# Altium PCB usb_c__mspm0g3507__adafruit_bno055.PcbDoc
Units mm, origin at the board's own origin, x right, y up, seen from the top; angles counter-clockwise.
Board outline 92 x 60 mm, 2 copper layers (Top, Bottom), stack 0 mm thick; 44 components, 36 nets, 224 pads, 74 vias.
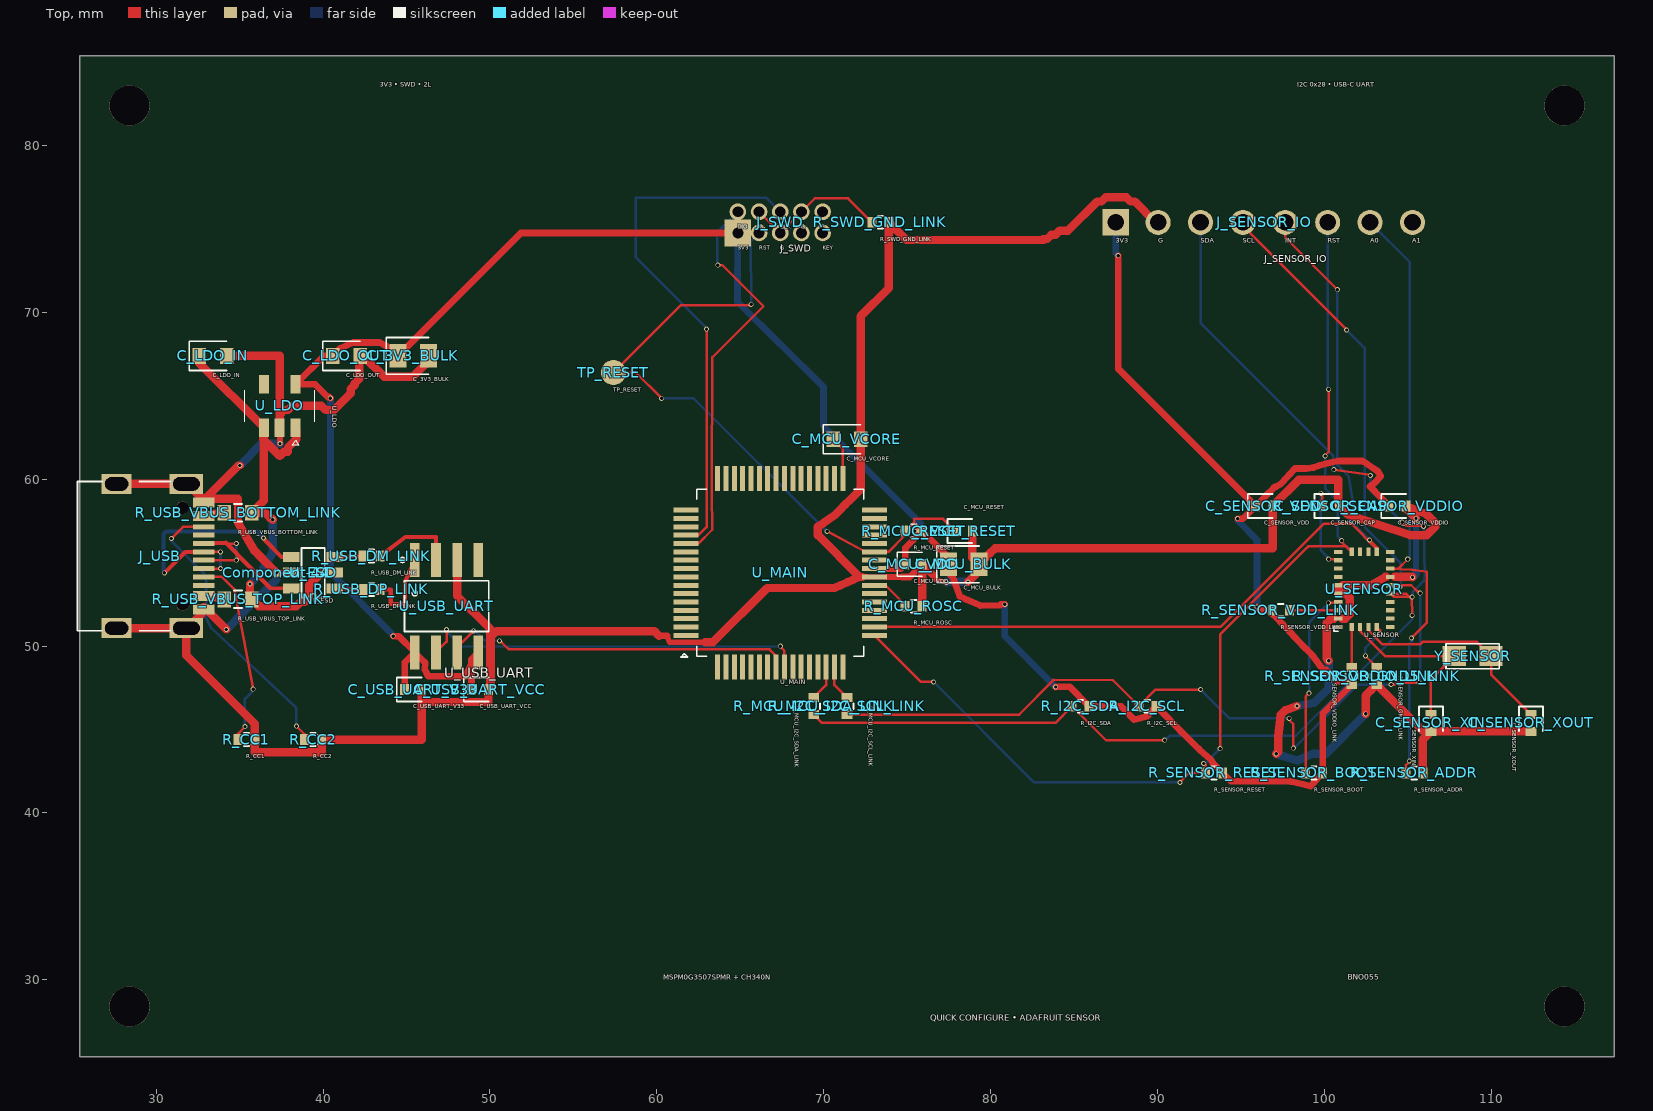
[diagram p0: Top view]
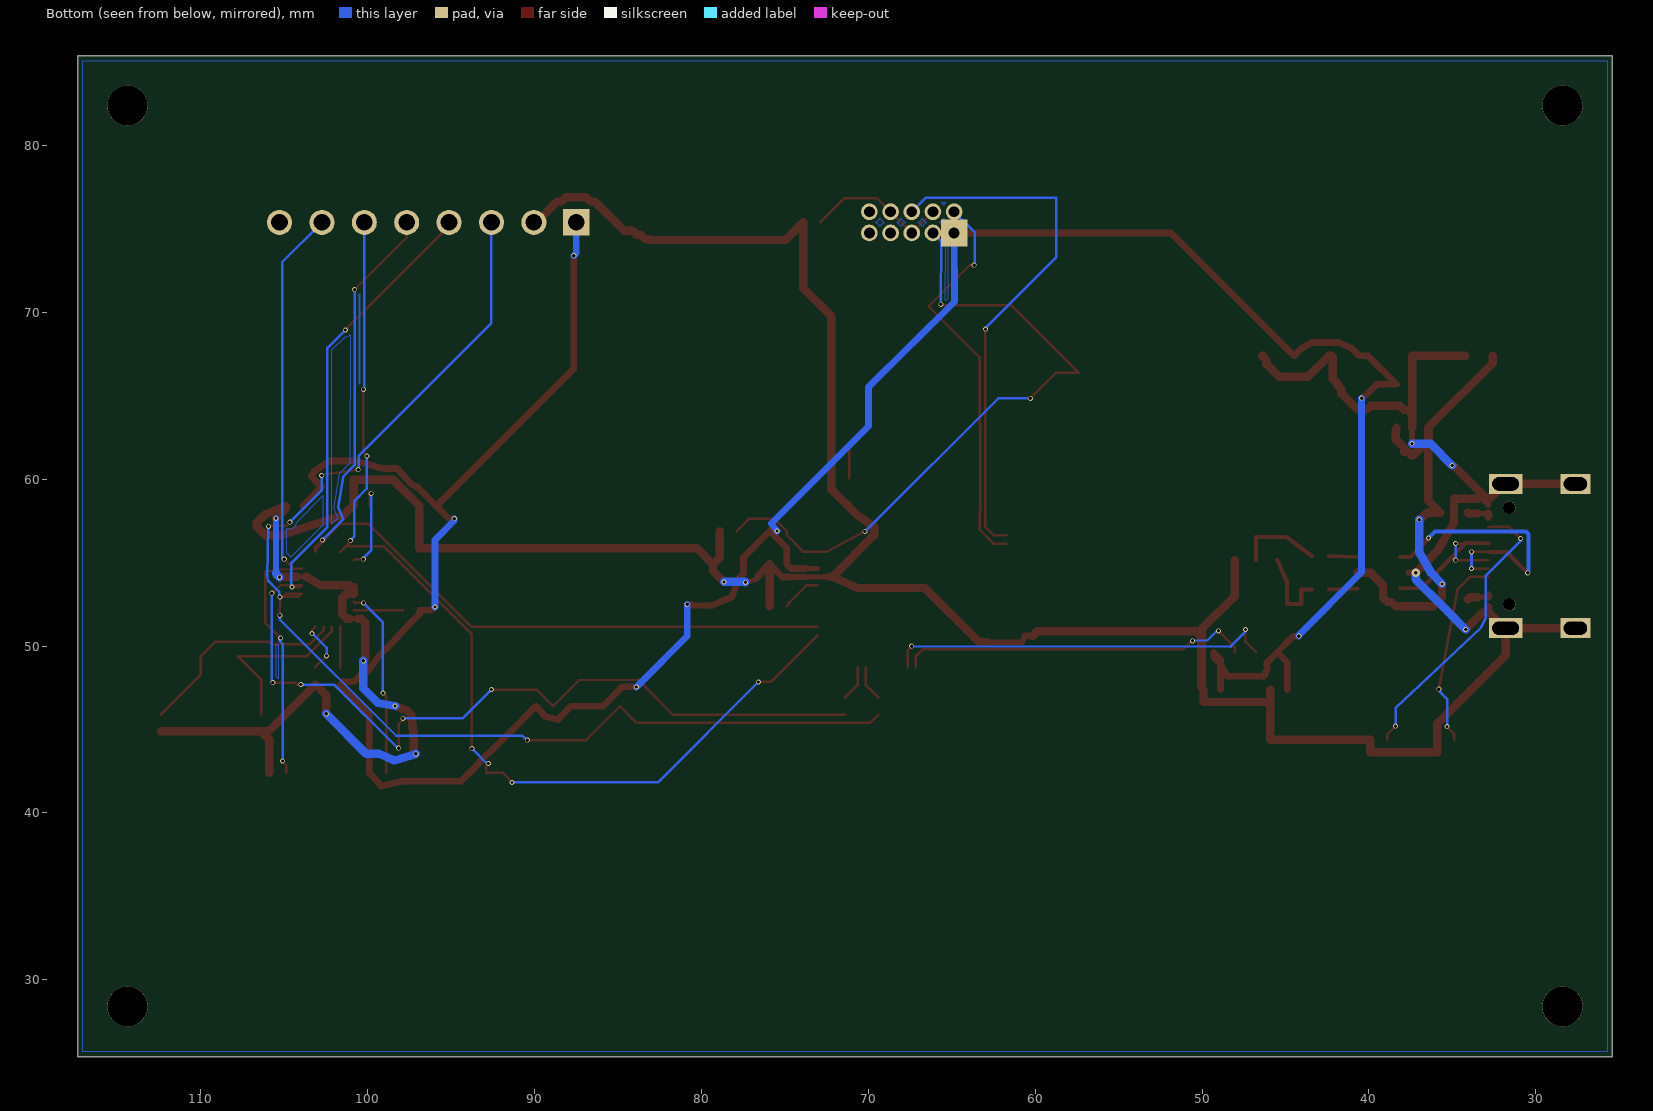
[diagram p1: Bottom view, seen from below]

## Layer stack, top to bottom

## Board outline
25.4,85.4 117.4,85.4 117.4,25.4 25.4,25.4

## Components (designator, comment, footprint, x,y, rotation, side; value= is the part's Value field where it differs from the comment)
C_3V3_BULK "" TSCIRCUIT-2.8500x1.4000mm 45.4,67.4 r0 top
C_LDO_IN "" TSCIRCUIT-2.4500x0.9500mm 33.4,67.4 r0 top
C_LDO_OUT "" TSCIRCUIT-2.4500x0.9500mm 41.4,67.4 r0 top
C_MCU_BULK "" TSCIRCUIT-2.8500x1.4000mm 78.4,54.9 r0 top
C_MCU_RESET "" TSCIRCUIT-1.5600x0.6400mm 78.4,56.9 r0 top
C_MCU_VCORE "" TSCIRCUIT-2.4500x0.9500mm 71.4,62.4 r0 top
C_MCU_VDD "" TSCIRCUIT-1.5600x0.6400mm 75.4,54.9 r0 top
C_SENSOR_CAP "" TSCIRCUIT-1.5600x0.6400mm 100.4,58.4 r0 top
C_SENSOR_VDD "" TSCIRCUIT-1.5600x0.6400mm 96.4,58.4 r0 top
C_SENSOR_VDDIO "" TSCIRCUIT-1.5600x0.6400mm 104.4,58.4 r0 top
C_SENSOR_XIN "" TSCIRCUIT-0.6400x1.5600mm 106.4,45.4 r270 top
C_SENSOR_XOUT "" TSCIRCUIT-0.6400x1.5600mm 112.4,45.4 r270 top
C_USB_UART_V33 "" TSCIRCUIT-1.5600x0.6400mm 45.4,47.4 r0 top
C_USB_UART_VCC "" TSCIRCUIT-1.5600x0.6400mm 49.4,47.4 r0 top
Component-44 "" TSCIRCUIT-0.5000x0.5000mm 37.2,54.4 r0 top
J_SENSOR_IO "" TSCIRCUIT-19.2800x1.5000mm 96.4,75.4 r0 top
J_SWD "" TSCIRCUIT-6.0800x2.2700mm 67.4,75.4 r0 top
J_USB "" TSCIRCUIT-6.7732x9.8502mm 30.113,55.4 r90 top
R_CC1 "" TSCIRCUIT-1.5600x0.6400mm 35.4,44.4 r0 top
R_CC2 "" TSCIRCUIT-1.5600x0.6400mm 39.4,44.4 r0 top
R_I2C_SCL "" TSCIRCUIT-1.5600x0.6400mm 89.4,46.4 r0 top
R_I2C_SDA "" TSCIRCUIT-1.5600x0.6400mm 85.4,46.4 r0 top
R_MCU_I2C_SCL_LINK "" TSCIRCUIT-0.6400x1.5600mm 71.4,46.4 r270 top
R_MCU_I2C_SDA_LINK "" TSCIRCUIT-0.6400x1.5600mm 69.4,46.4 r270 top
R_MCU_RESET "" TSCIRCUIT-1.5600x0.6400mm 75.4,56.9 r0 top
R_MCU_ROSC "" TSCIRCUIT-1.5600x0.6400mm 75.4,52.4 r0 top
R_SENSOR_ADDR "" TSCIRCUIT-1.5600x0.6400mm 105.4,42.4 r0 top
R_SENSOR_BOOT "" TSCIRCUIT-1.5600x0.6400mm 99.4,42.4 r0 top
R_SENSOR_GND5_LINK "" TSCIRCUIT-0.6400x1.5600mm 103.15,48.2 r270 top
R_SENSOR_RESET "" TSCIRCUIT-1.5600x0.6400mm 93.4,42.4 r0 top
R_SENSOR_VDD_LINK "" TSCIRCUIT-1.5600x0.6400mm 97.4,52.15 r0 top
R_SENSOR_VDDIO_LINK "" TSCIRCUIT-0.6400x1.5600mm 101.65,48.2 r270 top
R_SWD_GND_LINK "" TSCIRCUIT-1.5600x0.6400mm 73.4,75.4 r0 top
R_USB_DM_LINK "" TSCIRCUIT-1.5600x0.6400mm 42.9,55.4 r0 top
R_USB_DP_LINK "" TSCIRCUIT-1.5600x0.6400mm 42.9,53.4 r0 top
R_USB_VBUS_BOTTOM_LINK "" TSCIRCUIT-2.4500x0.9500mm 34.9,58 r0 top
R_USB_VBUS_TOP_LINK "" TSCIRCUIT-2.4500x0.9500mm 34.9,52.8 r0 top
TP_RESET "" TSCIRCUIT-1.5000x1.5000mm 57.4,66.4 r0 top
U_ESD "" TSCIRCUIT-3.6000x2.5000mm 39.4,54.4 r0 top
U_LDO "" TSCIRCUIT-2.5000x3.7000mm 37.4,64.4 r270 top
U_MAIN "" TSCIRCUIT-12.8000x12.8000mm 67.4,54.4 r0 top
U_SENSOR "" TSCIRCUIT-3.6260x4.9999mm 102.4,53.4 r0 top
U_USB_UART "" TSCIRCUIT-4.3840x7.5712mm 47.4,52.4 r0 top
Y_SENSOR "" TSCIRCUIT-3.6000x1.2000mm 108.9,49.4 r0 top

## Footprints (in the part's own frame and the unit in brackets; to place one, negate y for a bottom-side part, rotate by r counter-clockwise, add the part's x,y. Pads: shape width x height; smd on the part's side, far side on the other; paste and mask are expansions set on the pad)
TSCIRCUIT-0.5000x0.5000mm [mm]
TSCIRCUIT-0.6400x1.5600mm [mm]
  rect 0.54x0.64 smd: 1(-0.51,0) 2(0.51,0)
  silkscreen extent -0.98,-0.72 0.51,0.72
TSCIRCUIT-1.5000x1.5000mm [mm]
  round 1.5 smd: 1(0,0)
TSCIRCUIT-1.5600x0.6400mm [mm]
  rect 0.54x0.64 smd: 1(-0.51,0) 2(0.51,0)
  silkscreen extent -0.98,-0.72 0.51,0.72
TSCIRCUIT-2.4500x0.9500mm [mm]
  rect 0.8x0.95 smd: 1(-0.825,0) 2(0.825,0)
  silkscreen extent -1.42,-0.87 0.82,0.87
TSCIRCUIT-2.5000x3.7000mm [mm]
  rect 1.1x0.6 smd: 1(1.3,0.95) 2(1.3,0) 3(1.3,-0.95) 4(-1.3,-0.95) 5(-1.3,0.95)
  silkscreen extent -0.95,-2.1 2.35,2.1
TSCIRCUIT-2.8500x1.4000mm [mm]
  rect 1.025x1.4 smd: 1(-0.913,0) 2(0.913,0)
  silkscreen extent -1.63,-1.1 0.91,1.1
TSCIRCUIT-3.6000x1.2000mm [mm]
  rect 1.4x1.2 smd: 1(-1.1,0) 2(1.1,0)
  silkscreen extent -1.6,-0.75 1.6,0.75
TSCIRCUIT-3.6000x2.5000mm [mm]
  rect 1x0.6 smd: 1(-1.3,-0.95) 2(-1.3,0) 3(-1.3,0.95) 4(1.3,0.95) 5(1.3,0) 6(1.3,-0.95)
  silkscreen extent -0.7,-1.49 0.7,1.49
TSCIRCUIT-3.6260x4.9999mm [mm]
  rect 0.5x0.25 smd: 1(-1.563,-2.25) 2(-1.563,-1.75) 3(-1.563,-1.25) 4(-1.563,-0.75) 5(-1.563,-0.25) 6(-1.563,0.25) 7(-1.563,0.75) 8(-1.563,1.25) 9(-1.563,1.75) 10(-1.563,2.25) 15(1.563,2.25) 16(1.563,1.75) 17(1.563,1.25) 18(1.563,0.75) 19(1.563,0.25) 20(1.563,-0.25) 21(1.563,-0.75) 22(1.563,-1.25) 23(1.563,-1.75) 24(1.563,-2.25)
  rect 0.25x0.5 smd: 11(-0.75,2.25) 12(-0.25,2.25) 13(0.25,2.25) 14(0.75,2.25) 25(0.75,-2.25) 26(0.25,-2.25) 27(-0.25,-2.25) 28(-0.75,-2.25)
  silkscreen extent -1.81,-2.5 -1.56,-2.25
TSCIRCUIT-4.3840x7.5712mm [mm]
  rect 0.574x2.036 smd: 1(-1.905,2.768) 2(-0.635,2.768) 3(0.635,2.768) 4(1.905,2.768) 5(1.905,-2.768) 6(0.635,-2.768) 7(-0.635,-2.768) 8(-1.905,-2.768)
  silkscreen extent -2.79,-1.52 2.53,2.92
TSCIRCUIT-6.0800x2.2700mm [mm]
  rect 1.6x1.6 hole 0.65: 1(-2.54,-0.635)
  round 1 hole 0.65: 2(-2.54,0.635) 3(-1.27,0.635) 4(0,0.635) 5(1.27,0.635) 6(2.54,0.635) 7(2.54,-0.635) 8(1.27,-0.635) 9(0,-0.635) 10(-1.27,-0.635)
TSCIRCUIT-6.7732x9.8502mm [mm]
  rect 0.3x1.3 smd: 1(-3.35,-2.737) 2(-3.05,-2.737) 3(-2.55,-2.737) 4(-2.25,-2.737) 5(-1.75,-2.737) 6(-1.25,-2.737) 7(-0.75,-2.737) 8(-0.25,-2.737) 9(0.25,-2.737) 10(0.75,-2.737) 11(1.25,-2.737) 12(1.75,-2.737) 13(2.55,-2.737) 14(2.25,-2.737) 15(3.35,-2.737) 16(3.05,-2.737)
  rect 1.2x2 hole 0.8 slot 1.6 at 90 deg: 17(-4.325,-1.693) 18(4.325,-1.693)
  rect 1.2x1.8 hole 0.8 slot 1.4 at 90 deg: 19(4.325,2.487) 20(-4.325,2.487)
  round 0.75 hole 0.75 unplated: NPTH-1(-2.9,-1.468) NPTH-2(2.9,-1.468)
  silkscreen extent -4.47,-0.75 4.47,4.83
TSCIRCUIT-12.8000x12.8000mm [mm]
  rect 1.5x0.3 smd: 1(-5.65,-3.75) 2(-5.65,-3.25) 3(-5.65,-2.75) 4(-5.65,-2.25) 5(-5.65,-1.75) 6(-5.65,-1.25) 7(-5.65,-0.75) 8(-5.65,-0.25) 9(-5.65,0.25) 10(-5.65,0.75) 11(-5.65,1.25) 12(-5.65,1.75) 13(-5.65,2.25) 14(-5.65,2.75) 15(-5.65,3.25) 16(-5.65,3.75) 33(5.65,3.75) 34(5.65,3.25) 35(5.65,2.75) 36(5.65,2.25) 37(5.65,1.75) 38(5.65,1.25) 39(5.65,0.75) 40(5.65,0.25) 41(5.65,-0.25) 42(5.65,-0.75) 43(5.65,-1.25) 44(5.65,-1.75) 45(5.65,-2.25) 46(5.65,-2.75) 47(5.65,-3.25) 48(5.65,-3.75)
  rect 0.3x1.5 smd: 17(-3.75,5.65) 18(-3.25,5.65) 19(-2.75,5.65) 20(-2.25,5.65) 21(-1.75,5.65) 22(-1.25,5.65) 23(-0.75,5.65) 24(-0.25,5.65) 25(0.25,5.65) 26(0.75,5.65) 27(1.25,5.65) 28(1.75,5.65) 29(2.25,5.65) 30(2.75,5.65) 31(3.25,5.65) 32(3.75,5.65) 49(3.75,-5.65) 50(3.25,-5.65) 51(2.75,-5.65) 52(2.25,-5.65) 53(1.75,-5.65) 54(1.25,-5.65) 55(0.75,-5.65) 56(0.25,-5.65) 57(-0.25,-5.65) 58(-0.75,-5.65) 59(-1.25,-5.65) 60(-1.75,-5.65) 61(-2.25,-5.65) 62(-2.75,-5.65) 63(-3.25,-5.65) 64(-3.75,-5.65)
  silkscreen extent -5.95,-5.05 5,5
TSCIRCUIT-19.2800x1.5000mm [mm]
  rect 1.6x1.6 hole 1: 1(-8.89,0)
  round 1.5 hole 1: 2(-6.35,0) 3(-3.81,0) 4(-1.27,0) 5(1.27,0) 6(3.81,0) 7(6.35,0) 8(8.89,0)

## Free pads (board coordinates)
  round 2.4 hole 2.4 unplated: NPTH-3(28.4,28.4) NPTH-4(114.4,28.4) NPTH-5(28.4,82.4) NPTH-6(114.4,82.4)

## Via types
v1: diameter 0.3, hole 0.2, Top to Bottom, 73 vias
v2: diameter 0.5, hole 0.2, Top to Bottom, 1 vias

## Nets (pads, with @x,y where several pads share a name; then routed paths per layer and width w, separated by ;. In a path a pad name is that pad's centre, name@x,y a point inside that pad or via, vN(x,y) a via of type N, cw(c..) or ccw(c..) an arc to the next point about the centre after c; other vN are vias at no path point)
".J_SWD > .pin2 to .U_MAIN > .pin12": J_SWD.2 U_MAIN.12 | length 24.1
  Top w0.15: U_MAIN.12 62.499,56.15 63.324,56.975 63.307,59.192 63.322,67.31 66.386,70.372 63.923,72.835 v1(63.659,72.835)
  Bottom w0.15: v1(63.659,72.835) 63.618,72.876 63.618,72.911 63.618,74.793 J_SWD.2
".J_SWD > .pin4 to .U_MAIN > .pin13": J_SWD.4 U_MAIN.13 | length 31.9
  Top w0.15: U_MAIN.13 61.752,56.652 62.497,56.652 62.984,57.139 v1(62.984,68.999)
  Bottom w0.15: v1(62.984,68.999) 62.924,69.059 62.924,69.128 58.745,73.307 58.745,76.868 66.567,76.868 J_SWD.4
".U_MAIN > .pin42 to .R_MCU_ROSC > .pin1": R_MCU_ROSC.1 U_MAIN.42 | length 2.4
  Top w0.15: U_MAIN.42 73.719,53.65 74.769,52.6 74.769,52.521 R_MCU_ROSC.1
".U_SENSOR > .CAP to .C_SENSOR_CAP > .pin1": C_SENSOR_CAP.1 U_SENSOR.9 | length 5.6
  Top w0.15: v1(99.8,59.158) 99.829,59.171 99.829,59.125 99.89,59.063 C_SENSOR_CAP.1 ; v1(100.265,55.21) 100.777,55.21 U_SENSOR.9
  Bottom w0.15: v1(99.8,59.158) 99.8,55.734 100.201,55.332 100.201,55.274 v1(100.265,55.21)
BNO055_GND5_LOCAL: R_SENSOR_GND5_LINK.1 U_SENSOR.25 | length 3.2
  Top w0.15: v1(102.474,49.417) 102.494,49.397 103.15,48.741 R_SENSOR_GND5_LINK.1 ; U_SENSOR.25 103.351,50.949 v1(103.351,50.747)
  Bottom w0.15: v1(102.474,49.417) 102.474,49.903 103.357,50.786 103.357,50.753 v1(103.351,50.747)
BNO055_VDD_LOCAL: R_SENSOR_VDD_LINK.2 U_SENSOR.3 | length 2.9
  Top w0.15: R_SENSOR_VDD_LINK.2 U_SENSOR.3@100.837,52.15
BNO055_VDDIO_LOCAL: R_SENSOR_VDDIO_LINK.1 U_SENSOR.28 | length 2.4
  Top w0.15: R_SENSOR_VDDIO_LINK.1 U_SENSOR.28
GND: C_3V3_BULK.2 C_LDO_IN.2 C_LDO_OUT.2 C_MCU_BULK.2 C_MCU_RESET.2 C_MCU_VCORE.2 C_MCU_VDD.2 C_SENSOR_CAP.2 C_SENSOR_VDD.2 C_SENSOR_VDDIO.2 C_SENSOR_XIN.2 C_SENSOR_XOUT.2 C_USB_UART_V33.2 C_USB_UART_VCC.2 J_SENSOR_IO.2 J_USB.1 J_USB.2 J_USB.15 J_USB.16 J_USB.17 J_USB.18 J_USB.19 J_USB.20 R_CC1.2 R_CC2.2 R_MCU_ROSC.2 R_SENSOR_ADDR.2 R_SENSOR_GND5_LINK.2 R_SWD_GND_LINK.2 U_ESD.2 U_LDO.2 U_MAIN.41 U_SENSOR.2 U_SENSOR.5 U_SENSOR.6 U_SENSOR.18 U_USB_UART.3 | length 255.3
  Top w0.25: U_SENSOR.2@100.587,51.65 U_SENSOR.2 101.087,51.65 ; U_SENSOR.5 101.087,53.15 ; 100.837,53.525 U_SENSOR.6 100.931,53.65 101.024,53.65 101.087,53.65 101.118,53.65 ; U_SENSOR.18@103.713,54.15 U_SENSOR.18 104.213,54.15
  Top w0.275: J_USB.16 J_USB.15@33.04,58.641
  Top w0.3: J_USB.1@32.699,51.9 J_USB.1 J_USB.1@32.849,52.2 ; J_USB.15@32.699,58.9 J_USB.15 ; J_USB.2 32.999,52.2 33.187,52.013 J_USB.1@33.189,52.013 ; J_USB.16@32.849,58.6 J_USB.15 ; J_USB.15@32.999,58.9 J_USB.15 ; J_USB.15@33.04,58.641 33.231,58.832 33.499,58.832 ; U_MAIN.41@72.626,54.155 U_MAIN.41 73.144,54.15 73.237,54.15 73.331,54.15 73.425,54.15 73.519,54.15 73.612,54.15 73.706,54.15 U_MAIN.41@73.8,54.15
  Top w0.312: 76.713,53.994 77.04,53.912 v1(77.368,53.83)
  Top w0.314: U_MAIN.41@72.387,54.144 72.718,54.147 U_MAIN.41
  Top w0.318: 72.3,54.159 U_MAIN.41@72.626,54.155
  Top w0.325: J_USB.16 J_USB.16@32.849,58.6 ; 60.614,50.618 60.775,50.244 60.996,50.235 61.47,50.235 61.945,50.235 62.419,50.236 62.893,50.236 ; 76.602,54.208 76.713,53.994
  Top w0.35: U_LDO.2 37.409,62.619 37.409,62.144 v1(37.415,62.138)
  Top w0.375: U_MAIN.41@73.8,54.15 74.253,54.15 74.707,54.15
  Top w0.397: 72.3,54.149 U_MAIN.41@72.387,54.144
  Top w0.4: 37.2,54.4 U_ESD.2@37.6,54.4 ; 60.129,50.618 60.614,50.618 ; 74.707,54.15 75.16,54.15 75.41,54.4 75.66,54.65 C_MCU_VDD.2
  Top w0.45: 76.256,54.554 76.602,54.208
  Top w0.475: 71.811,53.992 72.202,54.16 72.3,54.159 ; 72.129,54.16 72.3,54.149
  Top w0.5: J_USB.20 J_USB.17 ; J_USB.19 J_USB.18 31.874,59.725 32.474,59.125 32.699,58.9 ; 32.699,51.9 32.474,51.675 31.874,51.075 J_USB.17 ; J_USB.1@32.849,52.2 J_USB.2 ; 32.999,58.9 34.924,60.825 v1(35.007,60.825) ; J_USB.1@33.189,52.013 v1(34.201,51.001) ; 33.499,58.832 34.9,58.832 34.9,57.4 35.909,55.691 36.232,55.368 36.555,55.045 36.877,54.723 37.2,54.4 ; C_LDO_IN.2 37.4,67.4 U_LDO.2 37.4,63.9 37.65,64.15 37.9,64.15 38.15,64.4 39.9,64.4 40.15,64.15 40.65,64.15 41.65,65.15 41.65,65.4 41.9,65.65 41.9,65.652 41.85,65.702 42.162,66.014 42.162,66.455 42.162,66.896 42.162,67.337 C_LDO_OUT.2 42.4,67.4 43.65,66.15 45.4,66.15 46.15,66.9 46.15,67.15 46.4,67.4 C_3V3_BULK.2 ; U_USB_UART.3 48.035,53.015 50.025,51.025 50.025,47.525 C_USB_UART_VCC.2@49.91,47.41 ; 60.129,50.618 59.846,50.9 50.4,50.9 50.067,50.567 50.067,47.567 C_USB_UART_VCC.2@49.91,47.41 ; 62.893,50.236 63.367,50.236 66.62,53.489 70.638,53.489 71.029,53.656 71.42,53.824 71.811,53.992 ; 72.129,54.16 72.129,54.171 69.65,56.65 69.65,57.15 69.991,57.387 70.332,57.624 70.673,57.861 70.983,58.171 71.294,58.482 71.604,58.792 71.915,59.103 72.225,59.413 72.225,59.911 72.225,60.409 72.225,60.907 72.225,61.404 72.225,61.902 C_MCU_VCORE.2 72.225,62.892 72.225,63.384 72.225,63.876 72.225,64.368 72.225,64.86 72.225,65.352 72.225,65.844 72.225,66.336 72.225,66.828 72.225,67.32 72.225,67.812 72.225,68.303 72.225,68.795 72.225,69.287 72.225,69.779 73.91,71.464 R_SWD_GND_LINK.2 74.262,75.048 74.613,74.697 74.965,74.345 74.987,74.345 75.47,74.345 75.953,74.345 76.436,74.345 76.919,74.345 77.402,74.345 77.885,74.345 78.368,74.345 78.851,74.345 79.335,74.345 79.818,74.345 80.301,74.345 80.784,74.345 81.267,74.345 81.75,74.345 82.233,74.345 82.716,74.345 83.199,74.345 83.15,74.394 83.15,74.4 83.4,74.4 83.65,74.65 83.9,74.65 84.15,74.9 84.65,74.9 86.4,76.65 86.65,76.65 86.9,76.9 88.15,76.9 88.4,76.65 88.65,76.65 89.9,75.4 J_SENSOR_IO.2 ; R_MCU_ROSC.2 C_MCU_VDD.2 76.256,54.554 ; v1(78.65,53.85) 79.313,54.512 C_MCU_BULK.2 ; C_MCU_RESET.2 78.91,55.303 C_MCU_BULK.2 ; v1(97.123,43.55) 97.25,43.676 97.25,44.585 97.4,45.9 97.65,46.15 v1(98.367,46.412) ; v1(100.269,49.122) 100.15,49.24 100.15,51.4 100.4,51.65 U_SENSOR.2@100.587,51.65 ; U_SENSOR.5 100.837,53.275 100.837,53.525 ; 101.087,51.65 101.275,51.65 101.525,51.9 101.525,52.9 101.275,53.15 101.087,53.15 ; 101.118,53.65 101.212,53.65 101.306,53.65 101.4,53.65 101.493,53.65 101.587,53.65 101.994,53.65 102.401,53.65 102.807,53.65 103.65,54.15 103.713,54.15 ; v1(102.487,45.94) 102.487,46.302 102.487,46.665 102.487,47.027 102.818,47.359 R_SENSOR_GND5_LINK.2 105.95,44.89 C_SENSOR_XIN.2 ; 104.213,54.15 105.27,54.15 v1(105.291,54.128) ; v1(105.503,57.662) 105.49,57.675 105.2,57.965 104.91,58.255 C_SENSOR_VDDIO.2 104.906,58.396 106.15,57.9 106.65,57.4 106.65,57.15 106.15,56.65 105.15,56.65 101.405,57.896 101.157,58.148 C_SENSOR_CAP.2 100.844,58.466 100.844,59.967 98.477,59.967 C_SENSOR_VDD.2 96.91,55.86 91.723,55.86 91.225,55.86 90.727,55.86 90.23,55.86 89.732,55.86 89.234,55.86 88.736,55.86 88.238,55.86 87.741,55.86 87.243,55.86 86.745,55.86 86.247,55.86 85.749,55.86 85.251,55.86 84.754,55.86 84.256,55.86 83.758,55.86 83.26,55.86 82.762,55.86 82.265,55.86 81.767,55.86 81.269,55.86 80.771,55.86 80.273,55.86 79.953,55.54 79.633,55.22 C_MCU_BULK.2 ; R_SENSOR_ADDR.2 105.91,44.4 C_SENSOR_XIN.2 ; C_SENSOR_XOUT.2 C_SENSOR_XIN.2 ; J_USB.17 31.806,49.444 35.908,45.341 35.909,44.871 R_CC1.2 35.91,43.65 39.91,43.65 R_CC2.2 40.41,44.4 40.91,44.4 45.91,44.4 C_USB_UART_V33.2 45.91,46.65 49.91,46.65 C_USB_UART_VCC.2 ; C_USB_UART_VCC.2 C_USB_UART_VCC.2@49.91,47.41 ; C_USB_UART_VCC.2 C_USB_UART_VCC.2@49.91,47.41
  Bottom w0.375: 105.503,54.409 105.503,54.874 105.503,55.339 105.503,55.803 105.503,56.268 105.503,56.733 105.503,57.197 v1(105.503,57.662)
  Bottom w0.5: v1(34.201,51.001) 34.262,51.062 34.589,51.389 34.915,51.715 35.242,52.042 35.568,52.368 35.894,52.694 36.221,53.021 36.547,53.347 36.874,53.674 37.2,54 37.2,54.4 ; v1(35.007,60.825) 36.32,62.138 v1(37.415,62.138) ; v1(77.368,53.83) 77.388,53.85 v1(78.65,53.85) ; v1(97.123,43.55) 98.4,43.15 99.317,43.55 100.097,43.55 v1(102.487,45.94) ; v1(98.367,46.412) 99.4,46.6 100.269,47.469 v1(100.269,49.122) ; v1(105.291,54.128) 105.503,54.34 105.503,54.409
MAIN_RESET: C_MCU_RESET.1 J_SWD.10 R_MCU_RESET.1 TP_RESET.1 U_MAIN.38 | length 40.6
  Top w0.15: v1(60.288,64.85) 60.277,64.861 58.738,66.4 TP_RESET.1 61.44,70.44 65.476,70.44 65.616,70.44 v1(65.661,70.485) ; v1(70.215,56.88) 72.515,55.65 U_MAIN.38 73.889,55.65 74.889,56.651 R_MCU_RESET.1@74.889,56.899 ; R_MCU_RESET.1 75.442,57.452 75.442,57.636 77.166,57.628 C_MCU_RESET.1
  Bottom w0.15: v1(60.288,64.85) 62.215,64.85 70.044,57.021 70.074,57.021 v1(70.215,56.88) ; v1(65.661,70.485) 65.641,74.276 J_SWD.10
MCU_I2C_SCL_LOCAL: R_MCU_I2C_SCL_LINK.1 U_MAIN.50 | length 2.2
  Top w0.15: U_MAIN.50 70.65,47.66 R_MCU_I2C_SCL_LINK.1
MCU_I2C_SDA_LOCAL: R_MCU_I2C_SDA_LINK.1 U_MAIN.51 | length 2.2
  Top w0.15: R_MCU_I2C_SDA_LINK.1 70.15,47.66 U_MAIN.51
MSPM0_VCORE: C_MCU_VCORE.1 U_MAIN.32 | length 2.6
  Top w0.15: C_MCU_VCORE.1 71.15,61.825 U_MAIN.32
SENSOR_ADDR0: J_SENSOR_IO.7 R_SENSOR_ADDR.1 U_SENSOR.17 | length 37.3
  Top w0.15: R_SENSOR_ADDR.1 104.89,42.853 105.1,43.063 v1(105.1,43.115) ; v1(105.01,55.209) 104.451,54.65 U_SENSOR.17 105.283,54.578 106.135,54.469 106.135,51.392 v1(105.228,50.485)
  Bottom w0.15: J_SENSOR_IO.7 105.131,73.019 105.131,55.377 105.131,55.33 v1(105.01,55.209) ; v1(105.1,43.115) 105.1,50.131 105.265,50.296 105.265,50.448 v1(105.228,50.485)
SENSOR_ADDR1: J_SENSOR_IO.8
SENSOR_BOOT: R_SENSOR_BOOT.1 U_SENSOR.4 | length 11.4
  Top w0.15: R_SENSOR_BOOT.1 98.89,46.976 99.008,47.094 v1(99.095,47.181) ; v1(100.247,52.596) 100.783,52.596 U_SENSOR.4
  Bottom w0.15: v1(99.095,47.181) 99.095,51.429 100.163,52.498 100.163,52.512 v1(100.247,52.596)
SENSOR_INT: J_SENSOR_IO.5 U_MAIN.47 U_SENSOR.14 | length 55.6
  Top w0.15: U_MAIN.47 93.782,51.15 99.982,57.35 101.628,57.35 103.114,55.864 103.114,55.686 U_SENSOR.14 103.15,55.931 v1(102.723,56.358) ; J_SENSOR_IO.5 97.67,74.489 100.738,71.421 v1(100.791,71.368)
  Bottom w0.15: v1(100.791,71.368) 100.796,60.85 101.483,60.156 101.775,58.325 101.483,57.599 v1@102.679,56.403 ; v1@102.679,56.402 v1(102.723,56.358)
SENSOR_RESET: J_SENSOR_IO.6 R_SENSOR_RESET.1 U_MAIN.48 U_SENSOR.11 | length 63.3
  Top w0.15: U_MAIN.48 75.848,47.852 v1(76.597,47.852) ; v1(91.357,41.83) 91.364,41.837 91.364,41.867 91.897,42.4 R_SENSOR_RESET.1 92.89,42.88 92.876,42.894 92.876,42.959 v1(92.78,42.965) ; v1(93.766,43.859) 93.766,50.692 99.008,55.934 99.069,55.996 101.295,55.996 101.304,55.996 U_SENSOR.11 101.046,56.254 v1(101.046,56.32) ; v1(100.063,61.393) 100.096,61.426 100.096,61.471 100.272,61.647 v1(100.272,65.397)
  Bottom w0.15: v1(76.597,47.852) 76.602,47.847 82.619,41.83 v1(91.357,41.83) ; v1(92.78,42.965) 92.917,43.01 93.734,43.827 v1(93.766,43.859) ; v1(100.063,61.393) 100.063,59.447 100.807,58.703 100.807,56.586 100.9,56.493 100.9,56.466 v1(101.046,56.32) ; J_SENSOR_IO.6 100.21,65.459 100.251,65.418 v1(100.272,65.397)
SENSOR_SCL: J_SENSOR_IO.4 R_I2C_SCL.1 R_MCU_I2C_SCL_LINK.2 U_SENSOR.19 | length 74
  Top w0.15: R_MCU_I2C_SCL_LINK.2 81.723,45.892 83.773,47.978 87.332,47.958 R_I2C_SCL.1 89.89,47.4 v1(92.6,47.4) ; J_SENSOR_IO.4 95.13,75.171 101.332,68.969 v1(101.351,68.95) ; v1(97.907,45.67) 97.937,45.64 97.937,45.548 98.148,45.337 v1(98.148,43.89) ; v1(104.012,47.7) 104.24,47.701 104.353,47.814 v1(105.691,47.814) ; v1(104.543,53.544) 104.069,53.544 U_SENSOR.19 105.22,53.65 105.568,53.301 105.628,53.301 v1(105.756,53.173)
  Bottom w0.15: v1(92.6,47.4) 92.622,47.378 94.329,45.671 v1(97.907,45.67) ; v1(98.148,43.89) 98.177,43.86 102.017,47.7 v1(104.012,47.7) ; v1(101.351,68.95) 102.423,67.878 102.423,57.146 104.58,54.989 104.58,53.649 104.58,53.581 v1(104.543,53.544) ; v1(105.691,47.814) 105.756,47.879 105.756,47.923 v1(105.756,53.173)
SENSOR_SDA: J_SENSOR_IO.3 R_I2C_SDA.1 R_MCU_I2C_SDA_LINK.2 U_SENSOR.20 | length 74.3
  Top w0.15: R_MCU_I2C_SDA_LINK.2 69.891,45.399 83.889,45.399 R_I2C_SDA.1 86.928,44.362 v1(90.445,44.362) ; v1(100.584,60.579) 102.712,60.285 v1(102.767,60.23) ; v1(104.672,57.427) 104.883,57.216 105.831,57.216 105.926,57.216 v1(105.956,57.186) ; v1(105.275,51.85) 105.261,52.932 105.123,52.932 104.905,53.15 U_SENSOR.20 104.162,52.966 v1(105.279,52.951)
  Bottom w0.15: v1(90.445,44.362) 90.582,44.499 90.603,44.499 90.732,44.628 98.298,44.628 105.279,51.609 v1(105.275,51.85) ; J_SENSOR_IO.3 92.59,69.366 100.344,61.612 100.53,61.424 100.531,60.691 100.532,60.637 v1(100.584,60.579) ; v1(102.767,60.23) 102.767,59.332 104.603,57.496 v1(104.672,57.427) ; v1(105.279,52.951) 105.324,52.996 105.324,53.021 105.324,53.263 105.501,53.44 105.956,53.895 106.043,54.194 v1(105.956,57.186)
SENSOR_XIN: C_SENSOR_XIN.1 U_SENSOR.27 Y_SENSOR.1 | length 10.6
  Top w0.15: U_SENSOR.27 102.155,51.145 102.155,50.903 103.658,49.4 Y_SENSOR.1 106.4,48 C_SENSOR_XIN.1
SENSOR_XOUT: C_SENSOR_XOUT.1 U_SENSOR.26 Y_SENSOR.2 | length 12.8
  Top w0.15: U_SENSOR.26 102.65,50.951 103.501,50.1 105.756,50.1 105.928,50.272 109.128,50.272 Y_SENSOR.2 110,48.31 C_SENSOR_XOUT.1
swd-ground-1-to-2: J_SWD.3 J_SWD.5 J_SWD.9 R_SWD_GND_LINK.1 | length 8.8
  Top w0.15: J_SWD.3 J_SWD.9 J_SWD.5 69.481,76.846 71.471,76.846 71.471,76.819 R_SWD_GND_LINK.1
UART_MSP_RX: U_MAIN.57 U_USB_UART.6 | length 21.1
  Top w0.15: U_USB_UART.6 48.034,49.927 v1(49.017,50.919) ; v1(50.576,50.314) 50.696,50.234 51.13,49.8 66.767,49.802 67.151,49.417 U_MAIN.57
  Bottom w0.15: v1(49.017,50.919) 49.063,50.954 49.077,50.954 49.677,50.354 v1(50.576,50.314)
UART_MSP_TX: U_MAIN.56 U_USB_UART.7 | length 23.5
  Top w0.15: U_USB_UART.7 47.4,50.267 v1(47.4,51) ; v1(67.402,49.995) 67.455,49.945 67.455,49.919 67.65,49.724 U_MAIN.56
  Bottom w0.15: v1(47.4,51) 47.4,50.886 48.286,49.972 v1(67.402,49.995)
usb-dm-device: R_USB_DM_LINK.1 U_ESD.4 | length 1.7
  Top w0.25: U_ESD.4 R_USB_DM_LINK.1
usb-dm-port-tie: J_USB.7 J_USB.9 U_ESD.3 | length 16.6
  Top w0.15: J_USB.7 v1(33.85,54.65) ; J_USB.9 v1(33.85,55.65)
  Top w0.25: v1(30.484,54.396) 31.738,55.65 J_USB.9 ; v1(36.431,56.479) 36.513,56.397 36.513,56.347 37.51,55.35 U_ESD.3
  Bottom w0.15: v1(33.85,54.65) v1(33.85,55.65)
  Bottom w0.25: v1(30.484,54.396) 30.432,54.448 30.432,54.464 30.432,56.712 30.597,56.878 36.032,56.878 v1(36.431,56.479)
usb-dm-uart: R_USB_DM_LINK.2 U_USB_UART.2 | length 5.1
  Top w0.25: R_USB_DM_LINK.2 44.95,56.55 46.765,56.55 U_USB_UART.2
usb-dp-device: R_USB_DP_LINK.1 U_ESD.6 | length 1.7
  Top w0.25: U_ESD.6 R_USB_DP_LINK.1
usb-dp-port-tie: J_USB.8 J_USB.10 U_ESD.1 | length 11.3
  Top w0.15: J_USB.8 v1(34.8,55.15) ; J_USB.10 v1(34.8,56.15)
  Top w0.25: J_USB.10 34.167,56.218 36.83,53.481 U_ESD.1
  Bottom w0.15: v1(34.8,55.15) v1(34.8,56.15)
usb-dp-uart: R_USB_DP_LINK.2 U_USB_UART.1 | length 5.1
  Top w0.25: R_USB_DP_LINK.2 44.05,53.4 44.05,52.53 44.9,52.53 44.9,53.85 U_USB_UART.1
USB_CC1: J_USB.6 R_CC1.1 | length 11.6
  Top w0.15: J_USB.6 33.93,54.15 34.668,53.428 v1(35.803,47.427) ; R_CC1.1 34.89,44.747 35.313,45.17 v1(35.318,45.175)
  Bottom w0.15: v1(35.318,45.175) 35.318,46.835 35.735,47.251 35.735,47.358 v1(35.803,47.427)
USB_CC2: J_USB.12 R_CC2.1 | length 17.7
  Top w0.15: v1(30.903,56.455) 31.598,57.15 J_USB.12 ; v1(38.404,45.206) 38.409,45.201 38.89,44.72 R_CC2.1
  Bottom w0.15: v1(30.903,56.455) 30.879,56.431 30.879,56.336 33,54.216 33,51.706 33.262,51.125 38.404,46.302 v1(38.404,45.206)
USB_VBUS_BOTTOM_LOCAL: J_USB.13 J_USB.14 R_USB_VBUS_BOTTOM_LINK.1 | length 1.5
  Top w0.3: J_USB.14 J_USB.14@32.849,57.8 ; J_USB.13 32.927,57.95 33.005,57.95 33.083,57.95 33.161,57.95 33.239,57.95 33.317,57.95 33.394,57.95 33.472,57.95 33.499,57.95
  Top w0.475: J_USB.13@32.849,57.8 J_USB.13 ; 33.499,57.95 R_USB_VBUS_BOTTOM_LINK.1@33.762,57.95
  Top w0.5: R_USB_VBUS_BOTTOM_LINK.1@33.762,57.95 34.025,57.95 R_USB_VBUS_BOTTOM_LINK.1
USB_VBUS_TOP_LOCAL: J_USB.3 J_USB.4 R_USB_VBUS_TOP_LINK.1 | length 1.6
  Top w0.3: J_USB.4 32.849,53 J_USB.3 32.945,52.958 33.032,52.939 33.499,52.939
  Top w0.5: 33.499,52.939 33.675,52.939 33.936,52.939 R_USB_VBUS_TOP_LINK.1
VBUS5: C_LDO_IN.1 R_USB_VBUS_BOTTOM_LINK.2 R_USB_VBUS_TOP_LINK.2 U_ESD.5 U_LDO.1 U_LDO.3 | length 29
  Top w0.5: C_LDO_IN.1 32.575,66.975 U_LDO.3 ; v1(35.614,53.726) 35.614,53.318 35.614,52.911 R_USB_VBUS_TOP_LINK.2 36.056,52.469 36.125,52.4 38.4,52.4 38.65,52.65 38.9,52.65 39.15,52.9 39.15,53.65 39.9,54.4 U_ESD.5 ; v1(36.983,57.584) 36.894,57.673 36.84,57.673 36.513,58 36.119,58 R_USB_VBUS_BOTTOM_LINK.2 36.45,58.725 U_LDO.3 ; U_LDO.1 38.35,62.95 38.4,62.9 38.4,62.4 37.9,61.9 37.9,61.65 37.65,61.65 37.4,61.4 36.4,62.4 36.4,63.15 U_LDO.3
  Bottom w0.5: v1(35.614,53.726) 36.29,54.402 36.29,54.437 36.983,55.621 36.983,56.112 36.983,56.602 36.983,57.093 v1(36.983,57.584)
VCC_3V3: C_3V3_BULK.1 C_LDO_OUT.1 C_MCU_BULK.1 C_MCU_VDD.1 C_SENSOR_VDD.1 C_SENSOR_VDDIO.1 C_USB_UART_V33.1 C_USB_UART_VCC.1 J_SENSOR_IO.1 J_SWD.1 R_I2C_SCL.2 R_I2C_SDA.2 R_MCU_RESET.2 R_SENSOR_BOOT.2 R_SENSOR_RESET.2 R_SENSOR_VDD_LINK.1 R_SENSOR_VDDIO_LINK.2 U_LDO.5 U_MAIN.40 U_USB_UART.5 U_USB_UART.8 | length 174.8
  Top w0.3: U_MAIN.40 73.15,54.65 73.25,54.65 73.35,54.65 73.45,54.65 73.55,54.65 73.65,54.65 73.75,54.65 U_MAIN.40@73.8,54.65
  Top w0.4: v1(40.438,64.859) 40.363,64.934 40.281,64.934 39.514,65.7 U_LDO.5 40.05,67.4 C_LDO_OUT.1 40.795,67.622 41.016,67.843 41.8,68.2 43.4,68.2 44.047,67.841 44.267,67.62 C_3V3_BULK.1 51.853,74.765 J_SWD.1 ; v1(44.2,50.6) 44.527,50.6 U_USB_UART.8 ; C_USB_UART_V33.1 44.89,49.027 U_USB_UART.8 ; C_USB_UART_VCC.1 48.89,49.217 U_USB_UART.5 49.305,49.345 49.093,49.129 48.881,48.912 48.5,48.2 46.3,48.2 46.1,48.6 46.115,49.012 45.908,49.219 45.702,49.425 U_USB_UART.8 ; U_MAIN.40@73.8,54.65 73.85,54.65 74.64,54.65 C_MCU_VDD.1 74.89,55.88 R_MCU_RESET.2 ; v1(75.475,56.9) 75.82,56.99 R_MCU_RESET.2 ; v1(80.856,52.511) 80.853,52.508 80.634,52.508 80.574,52.448 79.394,52.428 78.174,52.965 77.805,53.973 77.746,54.095 77.486,54.373 C_MCU_BULK.1 77.488,55.323 R_MCU_RESET.2 ; v1(83.903,47.554) 84.735,47.575 R_I2C_SDA.2 86.293,46.4 86.675,46.4 87.058,46.4 87.44,46.4 87.823,46.4 88.03,46.192 88.6,45.6 89.4,45.8 R_I2C_SCL.2 90.097,46.233 90.369,45.959 90.641,45.686 90.914,45.412 91.186,45.138 91.459,44.864 91.731,44.59 92.003,44.317 92.276,44.043 92.548,43.769 93.2,43.2 93.365,42.948 93.638,42.674 R_SENSOR_RESET.2 94.158,42.152 94.405,41.904 94.802,41.903 95.199,41.901 95.596,41.9 95.993,41.899 96.39,41.897 96.787,41.896 97.184,41.895 97.581,41.893 97.978,41.892 99.2,41.6 99.663,42.152 R_SENSOR_BOOT.2 99.91,45.95 R_SENSOR_VDDIO_LINK.2 101.462,47.878 101.21,47.868 100.957,47.857 100.8,47.9 100.575,48.125 100.35,48.35 100.125,48.575 100,48.5 99.352,49.375 99.077,49.662 98.803,49.949 98.529,50.236 98.255,50.524 97.98,50.811 97.706,51.098 97.432,51.385 97.158,51.673 96.883,51.96 R_SENSOR_VDD_LINK.1 96.235,52.15 96.168,52.217 96.111,52.217 v1(95.977,52.351) ; v1(87.649,73.403) 87.649,66.641 C_SENSOR_VDD.1 ; v1(94.82,57.64) 95.13,57.64 C_SENSOR_VDD.1 ; C_SENSOR_VDDIO.1 103.661,58.634 103.432,58.868 103.204,59.103 102.975,59.337 102.746,59.571 102.973,59.736 103.4,60.2 103.2,60.5 102.9,60.7 102.6,60.9 102.3,61.1 101.94,61.1 101.58,61.1 101.22,61.1 100.86,61.1 100.333,61 99.749,60.838 99.374,60.706 98.93,60.644 98.25,60.65 97.416,59.73 97.114,59.551 97.034,59.544 96.805,59.315 96.576,59.086 96.347,58.857 96.119,58.629 C_SENSOR_VDD.1
  Bottom w0.4: v1(40.438,64.859) 40.438,54.431 44.2,50.669 v1(44.2,50.6) ; J_SWD.1 64.842,70.644 69.994,65.524 69.996,63.182 75.82,57.359 v1(75.475,56.9) ; v1(80.856,52.511) 80.856,50.602 83.748,47.71 v1(83.903,47.554) ; J_SENSOR_IO.1 87.51,73.547 87.614,73.443 87.614,73.438 v1(87.649,73.403) ; v1(94.82,57.64) 94.82,57.529 95.977,56.372 v1(95.977,52.351)
pads on no net: J_SWD.6 J_SWD.7 J_SWD.8 J_USB.5 J_USB.11 J_USB.NPTH-1 J_USB.NPTH-2 U_LDO.4 U_MAIN.1 U_MAIN.2 U_MAIN.3 U_MAIN.4 U_MAIN.5 U_MAIN.6 U_MAIN.7 U_MAIN.8 U_MAIN.9 U_MAIN.10 U_MAIN.11 U_MAIN.14 U_MAIN.15 U_MAIN.16 U_MAIN.17 U_MAIN.18 U_MAIN.19 U_MAIN.20 U_MAIN.21 U_MAIN.22 U_MAIN.23 U_MAIN.24 U_MAIN.25 U_MAIN.26 U_MAIN.27 U_MAIN.28 U_MAIN.29 U_MAIN.30 U_MAIN.31 U_MAIN.33 U_MAIN.34 U_MAIN.35 U_MAIN.36 U_MAIN.37 U_MAIN.39 U_MAIN.43 U_MAIN.44 U_MAIN.45 U_MAIN.46 U_MAIN.49 U_MAIN.52 U_MAIN.53 U_MAIN.54 U_MAIN.55 U_MAIN.58 U_MAIN.59 U_MAIN.60 U_MAIN.61 U_MAIN.62 U_MAIN.63 U_MAIN.64 U_SENSOR.1 U_SENSOR.7 U_SENSOR.8 U_SENSOR.10 U_SENSOR.12 U_SENSOR.13 U_SENSOR.15 U_SENSOR.16 U_SENSOR.21 U_SENSOR.22 U_SENSOR.23 U_SENSOR.24 U_USB_UART.4
copper on no net:
  other v2: 37.2,54.4

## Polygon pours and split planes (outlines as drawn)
GND on Bottom (solid): 117.1,85.1 25.7,85.1 25.7,25.7 117.1,25.7
GND on Bottom (solid): 65.633,76.593 65.357,76.593 65.39,76.565 65.484,76.452 65.495,76.43 65.506,76.452 65.6,76.565
GND on Bottom (solid): 65.495,75.64 65.484,75.618 65.399,75.515 65.591,75.515 65.506,75.618
GND on Bottom (solid): 65.61,75.496 65.61,75.304 65.713,75.389 65.735,75.4 65.713,75.411
GND on Bottom (solid): 69.305,75.64 69.294,75.618 69.2,75.505 69.087,75.411 69.065,75.4 69.087,75.389 69.2,75.295 69.294,75.182 69.305,75.16 69.316,75.182 69.41,75.295 69.523,75.389 69.545,75.4 69.523,75.411 69.41,75.505 69.316,75.618
GND on Bottom (solid): 68.035,75.64 68.024,75.618 67.93,75.505 67.817,75.411 67.795,75.4 67.817,75.389 67.93,75.295 68.024,75.182 68.035,75.16 68.046,75.182 68.14,75.295 68.253,75.389 68.275,75.4 68.253,75.411 68.14,75.505 68.046,75.618
GND on Bottom (solid): 66.765,75.64 66.754,75.618 66.66,75.505 66.547,75.411 66.525,75.4 66.547,75.389 66.66,75.295 66.754,75.182 66.765,75.16 66.776,75.182 66.87,75.295 66.983,75.389 67.005,75.4 66.983,75.411 66.87,75.505 66.776,75.618
GND on Bottom (solid): 65.367,74.015 65.257,74.015 65.242,70.81 65.336,70.717 65.378,70.768 65.385,70.773
GND on Bottom (solid): 100.485,71.113 100.485,65.735 100.494,65.73 100.519,65.709 100.516,71.079 100.508,71.085
GND on Bottom (solid): 101.067,68.668 101.071,60.963 101.678,60.349 101.711,60.308 101.737,60.261 101.752,60.209 101.753,60.199 101.754,60.199 102.047,58.368 102.046,58.368 102.05,58.325 102.045,58.271 102.03,58.222 101.806,57.665 102.148,57.323 102.148,67.764 101.361,68.551 101.351,68.55 101.273,68.558 101.198,68.58 101.129,68.617 101.068,68.667
GND on Bottom (solid): 102.698,59.012 102.698,57.26 104.63,55.328 104.64,55.362 104.677,55.431 104.727,55.492 104.788,55.542 104.856,55.578 104.856,57.074 104.825,57.057 104.75,57.035 104.672,57.027 104.594,57.035 104.519,57.057 104.45,57.094 104.389,57.144 104.339,57.205 104.302,57.274 104.28,57.349 104.272,57.427 104.273,57.437
GND on Bottom (solid): 105.481,50.128 105.459,50.101 105.375,50.017 105.375,48.056 105.408,48.097 105.469,48.147 105.481,48.153

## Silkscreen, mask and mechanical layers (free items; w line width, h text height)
Top Overlay:
  text "3V3 • SWD • 2L" at 43.4,83.4 h0.48
  text "I2C 0x28 • USB-C UART" at 98.4,83.4 h0.5
  text "MSPM0G3507SPMR + CH340N" at 60.4,29.9 h0.52
  text "BNO055" at 101.4,29.9 h0.55
  text "QUICK CONFIGURE • ADAFRUIT SENSOR" at 76.4,27.4 h0.65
